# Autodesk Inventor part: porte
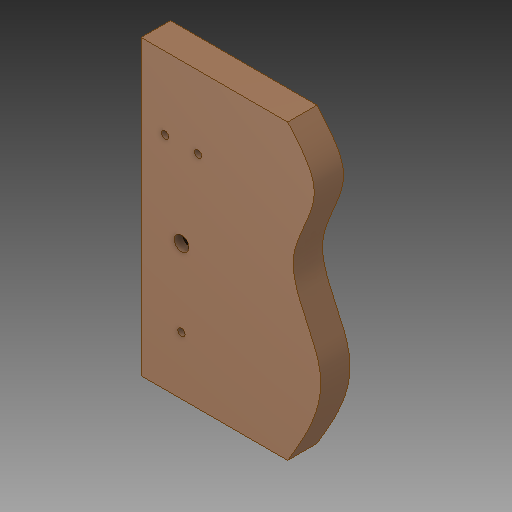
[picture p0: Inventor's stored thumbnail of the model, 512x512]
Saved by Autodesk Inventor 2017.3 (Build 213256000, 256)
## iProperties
Created: 2007-12
Part Number: porte
Material: solidworks materials|Chêne|72
Document SubType Name: Modeling
Designer: ficho
Density: 0.56 g/cm^3
Appearance: 143,89,29
Author: ficho
Sending System: SolidWorks 2009
Last Author: christophe
Last Saved: 2011-02-10
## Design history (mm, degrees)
feature "Enlèv. mat.-Extru.3"
node "Solide1"
